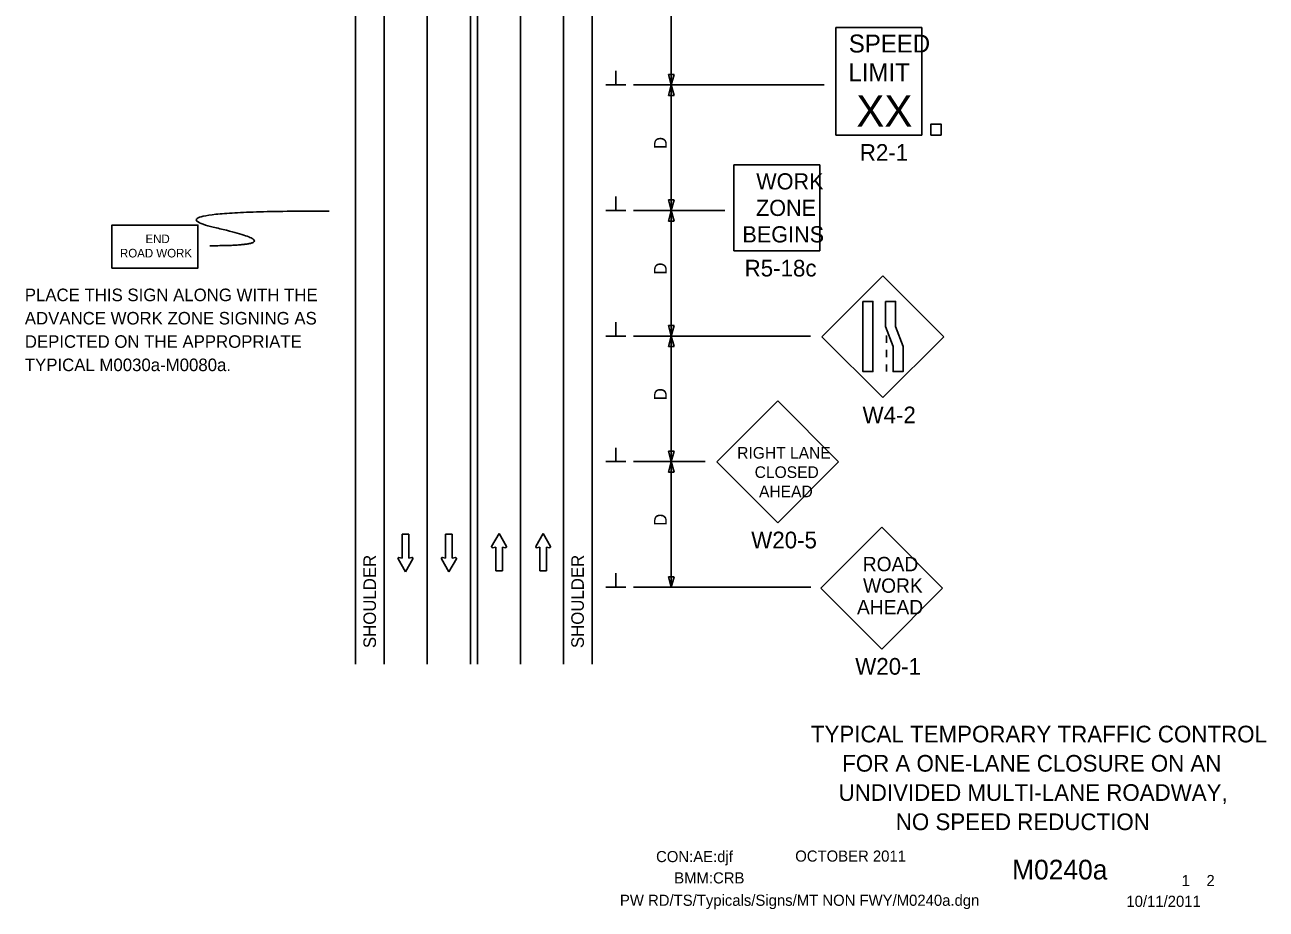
# Model space of a CAD drawing. Extents: x 16739 to 18475, y 7218 to 8197.
# Drawn here: x 16739 to 17431, y 7218 to 7711 of the extents above; entities that cross this region are included whole.
import ezdxf

# ---------------------------------------------------------------- set-up
doc = ezdxf.new("R2010")
doc.units = 0
for name, color, linetype in [('ALI_LEGAL_EX', 7, 'Continuous'), ('BORDER', 7, 'Continuous'), ('BORDER_SIGNAL_WO', 7, 'Continuous'), ('MT_SCRATCH_LEVEL_E', 7, 'Continuous'), ('PAVT_EDGE_EX', 7, 'Continuous'), ('TRAFFIC_SIGNS_PR', 7, 'Continuous'), ('TYPICAL_TEXT_DIMEN_PR', 7, 'Continuous')]:
    doc.layers.add(name, color=color, linetype=linetype)

msp = doc.modelspace()

# ---------------------------------------------------------------- linework, layer by layer
at = {"layer": 'ALI_LEGAL_EX'}
for points in [[(16963.15, 7683.87), (16963.15, 7658.87)], [(17015.15, 7683.87), (17015.15, 7658.87)], [(16963.15, 7583.87), (16963.15, 7558.87)], [(17015.15, 7583.87), (17015.15, 7558.87)], [(16963.15, 7483.87), (16963.15, 7458.87)], [(17015.15, 7483.87), (17015.15, 7458.87)], [(16963.15, 7358.87), (16963.15, 7383.87)], [(17015.15, 7383.87), (17015.15, 7358.87)]]:
    msp.add_lwpolyline(points, dxfattribs=at)
at = {"layer": 'MT_SCRATCH_LEVEL_E'}
for p, q in [((16952.82, 7427.05), (16949.08, 7427.05)), ((16949.08, 7427.05), (16949.08, 7413.79)), ((16952.82, 7427.05), (16949.08, 7427.05)), ((16949.08, 7427.05), (16949.08, 7413.79)), ((16952.82, 7413.79), (16952.82, 7427.05)), ((16952.82, 7413.79), (16952.82, 7427.05)), ((16977.08, 7427.05), (16973.34, 7427.05)), ((16973.34, 7427.05), (16973.34, 7413.79)), ((16977.08, 7427.05), (16973.34, 7427.05)), ((16973.34, 7427.05), (16973.34, 7413.79)), ((16977.08, 7413.79), (16977.08, 7427.05)), ((16977.08, 7413.79), (16977.08, 7427.05)), ((17003.12, 7427.51), (16999.01, 7420.27)), ((17003.12, 7427.51), (16999.01, 7420.27)), ((17007.27, 7420.27), (17003.12, 7427.51)), ((17007.27, 7420.27), (17003.12, 7427.51)), ((17027.68, 7427.51), (17023.57, 7420.27)), ((17027.68, 7427.51), (17023.57, 7420.27)), ((17031.83, 7420.27), (17027.68, 7427.51)), ((17031.83, 7420.27), (17027.68, 7427.51)), ((16946.82, 7413.43), (16950.97, 7406.18)), ((16946.82, 7413.43), (16950.97, 7406.18)), ((16949.08, 7413.79), (16947.3, 7414.11)), ((16949.08, 7413.79), (16947.3, 7414.11)), ((16950.97, 7406.18), (16955.08, 7413.43)), ((16950.97, 7406.18), (16955.08, 7413.43)), ((16954.6, 7414.11), (16952.82, 7413.79)), ((16954.6, 7414.11), (16952.82, 7413.79)), ((16971.08, 7413.43), (16975.23, 7406.18)), ((16971.08, 7413.43), (16975.23, 7406.18)), ((16973.34, 7413.79), (16971.56, 7414.11)), ((16973.34, 7413.79), (16971.56, 7414.11)), ((16975.23, 7406.18), (16979.34, 7413.43)), ((16975.23, 7406.18), (16979.34, 7413.43)), ((16978.86, 7414.11), (16977.08, 7413.79)), ((16978.86, 7414.11), (16977.08, 7413.79)), ((16999.49, 7419.59), (17001.27, 7419.9)), ((16999.49, 7419.59), (17001.27, 7419.9)), ((17001.27, 7419.9), (17001.27, 7406.65)), ((17001.27, 7419.9), (17001.27, 7406.65)), ((17005.01, 7406.65), (17005.01, 7419.9)), ((17005.01, 7419.9), (17006.79, 7419.59)), ((17005.01, 7406.65), (17005.01, 7419.9)), ((17005.01, 7419.9), (17006.79, 7419.59)), ((17024.05, 7419.59), (17025.83, 7419.9)), ((17024.05, 7419.59), (17025.83, 7419.9)), ((17025.83, 7419.9), (17025.83, 7406.65)), ((17025.83, 7419.9), (17025.83, 7406.65)), ((17029.57, 7406.65), (17029.57, 7419.9)), ((17029.57, 7419.9), (17031.35, 7419.59)), ((17029.57, 7406.65), (17029.57, 7419.9)), ((17029.57, 7419.9), (17031.35, 7419.59)), ((17001.27, 7406.65), (17005.01, 7406.65)), ((17001.27, 7406.65), (17005.01, 7406.65)), ((17025.83, 7406.65), (17029.57, 7406.65)), ((17025.83, 7406.65), (17029.57, 7406.65))]:
    msp.add_line(p, q, dxfattribs=at)
for centre, start, end in [((16999.42, 7420.05), 150.42484, 279.96381), ((16999.42, 7420.05), 150.42484, 279.96381), ((17006.86, 7420.05), 260.03619, 29.77312), ((17006.86, 7420.05), 260.03619, 29.77312), ((17023.98, 7420.05), 150.42484, 279.96381), ((17023.98, 7420.05), 150.42484, 279.96381), ((17031.42, 7420.05), 260.03619, 29.77312), ((17031.42, 7420.05), 260.03619, 29.77312), ((16947.23, 7413.65), 80.03619, 209.77312), ((16947.23, 7413.65), 80.03619, 209.77312), ((16954.67, 7413.65), 330.42484, 99.96381), ((16954.67, 7413.65), 330.42484, 99.96381), ((16971.49, 7413.65), 80.03619, 209.77312), ((16971.49, 7413.65), 80.03619, 209.77312), ((16978.93, 7413.65), 330.42484, 99.96381), ((16978.93, 7413.65), 330.42484, 99.96381)]:
    msp.add_arc(centre, 0.463, start, end, dxfattribs=at)
at = {"layer": 'PAVT_EDGE_EX'}
for p, q in [((16923.15, 8183.87), (16923.15, 7354.69)), ((16939.15, 8183.87), (16939.15, 7354.69)), ((16963.15, 8183.87), (16963.15, 7354.69)), ((16987.15, 8183.87), (16987.15, 7354.69)), ((16991.15, 8183.87), (16991.15, 7354.69)), ((17015.15, 8183.87), (17015.15, 7354.69)), ((17039.15, 8183.87), (17039.15, 7354.69)), ((17055.15, 8183.87), (17055.15, 7354.69))]:
    msp.add_line(p, q, dxfattribs=at)
msp.add_lwpolyline([(16963.15, 7358.87), (16963.15, 7383.87)], dxfattribs=at)
at = {"layer": 'TRAFFIC_SIGNS_PR'}
for p, q in [((17190.96, 7709.53), (17238.96, 7709.53)), ((17190.96, 7649.53), (17190.96, 7709.53)), ((17238.96, 7649.53), (17238.96, 7709.53)), ((17190.96, 7649.53), (17238.96, 7649.53)), ((17134.06, 7585.05), (17134.06, 7633.05)), ((17134.06, 7633.05), (17182.06, 7633.05)), ((17182.06, 7585.05), (17182.06, 7633.05)), ((17134.06, 7585.05), (17182.06, 7585.05)), ((17217.12, 7571.11), (17183.18, 7537.17)), ((17251.06, 7537.17), (17217.12, 7571.11)), ((17219.17, 7537.78), (17219.17, 7533.78)), ((17183.18, 7537.17), (17217.12, 7503.23)), ((17217.12, 7503.23), (17251.06, 7537.17)), ((17219.17, 7529.78), (17219.17, 7525.78)), ((17219.17, 7521.78), (17219.17, 7517.78)), ((17158.53, 7501.39), (17124.59, 7467.45)), ((17192.47, 7467.45), (17158.53, 7501.39)), ((17124.59, 7467.45), (17158.53, 7433.51)), ((17158.53, 7433.51), (17192.47, 7467.45)), ((17216.53, 7430.97), (17182.59, 7397.03)), ((17250.47, 7397.03), (17216.53, 7430.97)), ((17182.59, 7397.03), (17216.53, 7363.09)), ((17216.53, 7363.09), (17250.47, 7397.03))]:
    msp.add_line(p, q, dxfattribs=at)
for points in [[(17243.97, 7649.53), (17249.57, 7649.53), (17249.57, 7655.7), (17243.97, 7655.7)], [(16787.25, 7575.42), (16835.25, 7575.42), (16835.25, 7599.42), (16787.25, 7599.42)], [(17206, 7556.84), (17206, 7517.78), (17211.61, 7517.78), (17211.61, 7556.84)], [(17218.67, 7556.84), (17218.67, 7542.86), (17222.85, 7531.76), (17222.85, 7517.78), (17228.47, 7517.78), (17228.47, 7531.76), (17224.29, 7542.86), (17224.29, 7556.84)]]:
    msp.add_lwpolyline(points, close=True, dxfattribs=at)
msp.add_open_spline([(16841.88, 7587.9), (16889.11, 7587.9), (16804.09, 7607.24), (16908.36, 7607.24)], degree=2, dxfattribs=at)
at = {"layer": 'TYPICAL_TEXT_DIMEN_PR'}
for p, q in [((17099.15, 7747.53), (17099.15, 7677.53)), ((17068.28, 7677.53), (17068.28, 7685.31)), ((17099.15, 7677.53), (17097.58, 7683.39)), ((17097.58, 7683.39), (17099.15, 7683.39)), ((17099.15, 7683.39), (17100.72, 7683.39)), ((17100.72, 7683.39), (17099.15, 7677.53)), ((17073.9, 7677.53), (17062.65, 7677.53)), ((17184.39, 7677.53), (17078.15, 7677.53)), ((17097.58, 7671.67), (17099.15, 7677.53)), ((17099.15, 7677.53), (17099.15, 7607.53)), ((17099.15, 7677.53), (17100.72, 7671.67)), ((17099.15, 7671.67), (17097.58, 7671.67)), ((17100.72, 7671.67), (17099.15, 7671.67)), ((17068.28, 7607.53), (17068.28, 7615.31)), ((17073.9, 7607.53), (17062.65, 7607.53)), ((17129.12, 7607.53), (17078.15, 7607.53)), ((17099.15, 7607.53), (17097.58, 7613.39)), ((17097.58, 7613.39), (17099.15, 7613.39)), ((17097.58, 7601.67), (17099.15, 7607.53)), ((17099.15, 7613.39), (17100.72, 7613.39)), ((17100.72, 7613.39), (17099.15, 7607.53)), ((17099.15, 7607.53), (17099.15, 7537.53)), ((17099.15, 7607.53), (17100.72, 7601.67)), ((17099.15, 7601.67), (17097.58, 7601.67)), ((17100.72, 7601.67), (17099.15, 7601.67)), ((17068.28, 7537.53), (17068.28, 7545.31)), ((17099.15, 7537.53), (17097.58, 7543.39)), ((17097.58, 7543.39), (17099.15, 7543.39)), ((17099.15, 7543.39), (17100.72, 7543.39)), ((17100.72, 7543.39), (17099.15, 7537.53)), ((17073.9, 7537.53), (17062.65, 7537.53)), ((17176.83, 7537.53), (17078.15, 7537.53)), ((17097.58, 7531.67), (17099.15, 7537.53)), ((17099.15, 7531.67), (17097.58, 7531.67)), ((17099.15, 7537.53), (17099.15, 7467.53)), ((17099.15, 7537.53), (17100.72, 7531.67)), ((17100.72, 7531.67), (17099.15, 7531.67)), ((17068.28, 7467.53), (17068.28, 7475.31)), ((17099.15, 7467.53), (17097.58, 7473.39)), ((17097.58, 7473.39), (17099.15, 7473.39)), ((17099.15, 7473.39), (17100.72, 7473.39)), ((17100.72, 7473.39), (17099.15, 7467.53)), ((17073.9, 7467.53), (17062.65, 7467.53)), ((17118.08, 7467.53), (17078.15, 7467.53)), ((17097.58, 7461.67), (17099.15, 7467.53)), ((17099.15, 7461.67), (17097.58, 7461.67)), ((17099.15, 7467.53), (17099.15, 7397.53)), ((17099.15, 7467.53), (17100.72, 7461.67)), ((17100.72, 7461.67), (17099.15, 7461.67)), ((17068.28, 7397.53), (17068.28, 7405.31)), ((17099.15, 7397.53), (17097.58, 7403.39)), ((17097.58, 7403.39), (17099.15, 7403.39)), ((17099.15, 7403.39), (17100.72, 7403.39)), ((17100.72, 7403.39), (17099.15, 7397.53)), ((17073.9, 7397.53), (17062.65, 7397.53)), ((17176.98, 7397.53), (17078.15, 7397.53))]:
    msp.add_line(p, q, dxfattribs=at)

# ---------------------------------------------------------------- texts
at = {"layer": 'BORDER'}
for s, p in [('TYPICAL TEMPORARY TRAFFIC CONTROL', (17177.02, 7311.05)), ('FOR A ONE-LANE CLOSURE ON AN', (17194.46, 7294.75)), ('UNDIVIDED MULTI-LANE ROADWAY,', (17192.46, 7278.45)), ('NO SPEED REDUCTION ', (17224.35, 7262.15))]:
    msp.add_text(s, height=9.3, dxfattribs=at).set_placement(p)
at = {"layer": 'BORDER_SIGNAL_WO'}
for s, height, p in [('CON:AE:djf', 6.2, (17090.69, 7244.31)), ('    OCTOBER 2011    ', 6.2, (17159.08, 7244.59)), ('    M0240a   ', 11, (17272.86, 7234.63)), ('BMM:CRB   ', 6.2, (17100.81, 7232.42)), (' 1    2 ', 6.2, (17381.45, 7230.95)), ('PW RD/TS/Typicals/Signs/MT NON FWY/M0240a.dgn    ', 6.2, (17070.55, 7219.96)), ('10/11/2011    ', 6.2, (17352.93, 7219.38))]:
    msp.add_text(s, height=height, dxfattribs=at).set_placement(p)
at = {"layer": 'TRAFFIC_SIGNS_PR'}
for s, height, p in [('SPEED', 10, (17198.17, 7695.6)), ('LIMIT', 10, (17197.96, 7679.6)), ('XX', 17.538, (17202.35, 7654.22)), ('R2-1', 9.3, (17204.3, 7635.23)), ('WORK', 9.021, (17146.55, 7619.26)), ('ZONE', 9.021, (17146.41, 7604.49)), ('END', 4.789, (16806.01, 7589.34)), ('BEGINS', 9.021, (17138.82, 7589.73)), ('ROAD WORK', 4.789, (16791.77, 7581.36)), ('R5-18c', 9.3, (17140.07, 7570.75)), ('PLACE THIS SIGN ALONG WITH THE', 7, (16738.71, 7556.99)), ('ADVANCE WORK ZONE SIGNING AS', 7, (16738.71, 7543.99)), ('DEPICTED ON THE APPROPRIATE', 7, (16738.71, 7530.99)), ('TYPICAL M0030a-M0080a.', 7, (16738.71, 7517.99)), ('W4-2', 9.3, (17205.82, 7488.93)), ('RIGHT LANE', 6.5, (17135.93, 7469.19)), ('CLOSED', 6.5, (17145.67, 7458.44)), ('AHEAD', 6.5, (17148.11, 7447.69)), ('W20-5', 9.3, (17143.75, 7419.21)), ('ROAD', 8, (17205.96, 7406.45)), ('WORK', 8, (17206.1, 7394.45)), ('AHEAD', 8, (17202.73, 7382.45)), ('W20-1', 9.3, (17201.75, 7348.79))]:
    msp.add_text(s, height=height, dxfattribs=at).set_placement(p)
at = {"layer": 'TYPICAL_TEXT_DIMEN_PR'}
for s, p in [('D', (17096.59, 7641.75)), ('D', (17096.59, 7571.75)), ('D', (17096.59, 7501.75)), ('D', (17096.59, 7431.75)), ('SHOULDER', (16934.53, 7363.62)), ('SHOULDER', (17050.43, 7363.62))]:
    msp.add_text(s, height=7, rotation=90, dxfattribs=at).set_placement(p)

doc.saveas('drawing.dxf')
